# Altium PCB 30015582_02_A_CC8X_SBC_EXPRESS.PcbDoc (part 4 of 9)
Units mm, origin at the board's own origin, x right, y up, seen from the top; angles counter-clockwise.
Board outline 87 x 63 mm, 6 copper layers (Top Layer-L1, GND Plane-L2, Signal-L3, PWR/Signal-L4, GND Plane-L5, Bottom Layer-L6), stack 1.172 mm thick; 169 components, 171 nets, 693 pads, 391 vias.
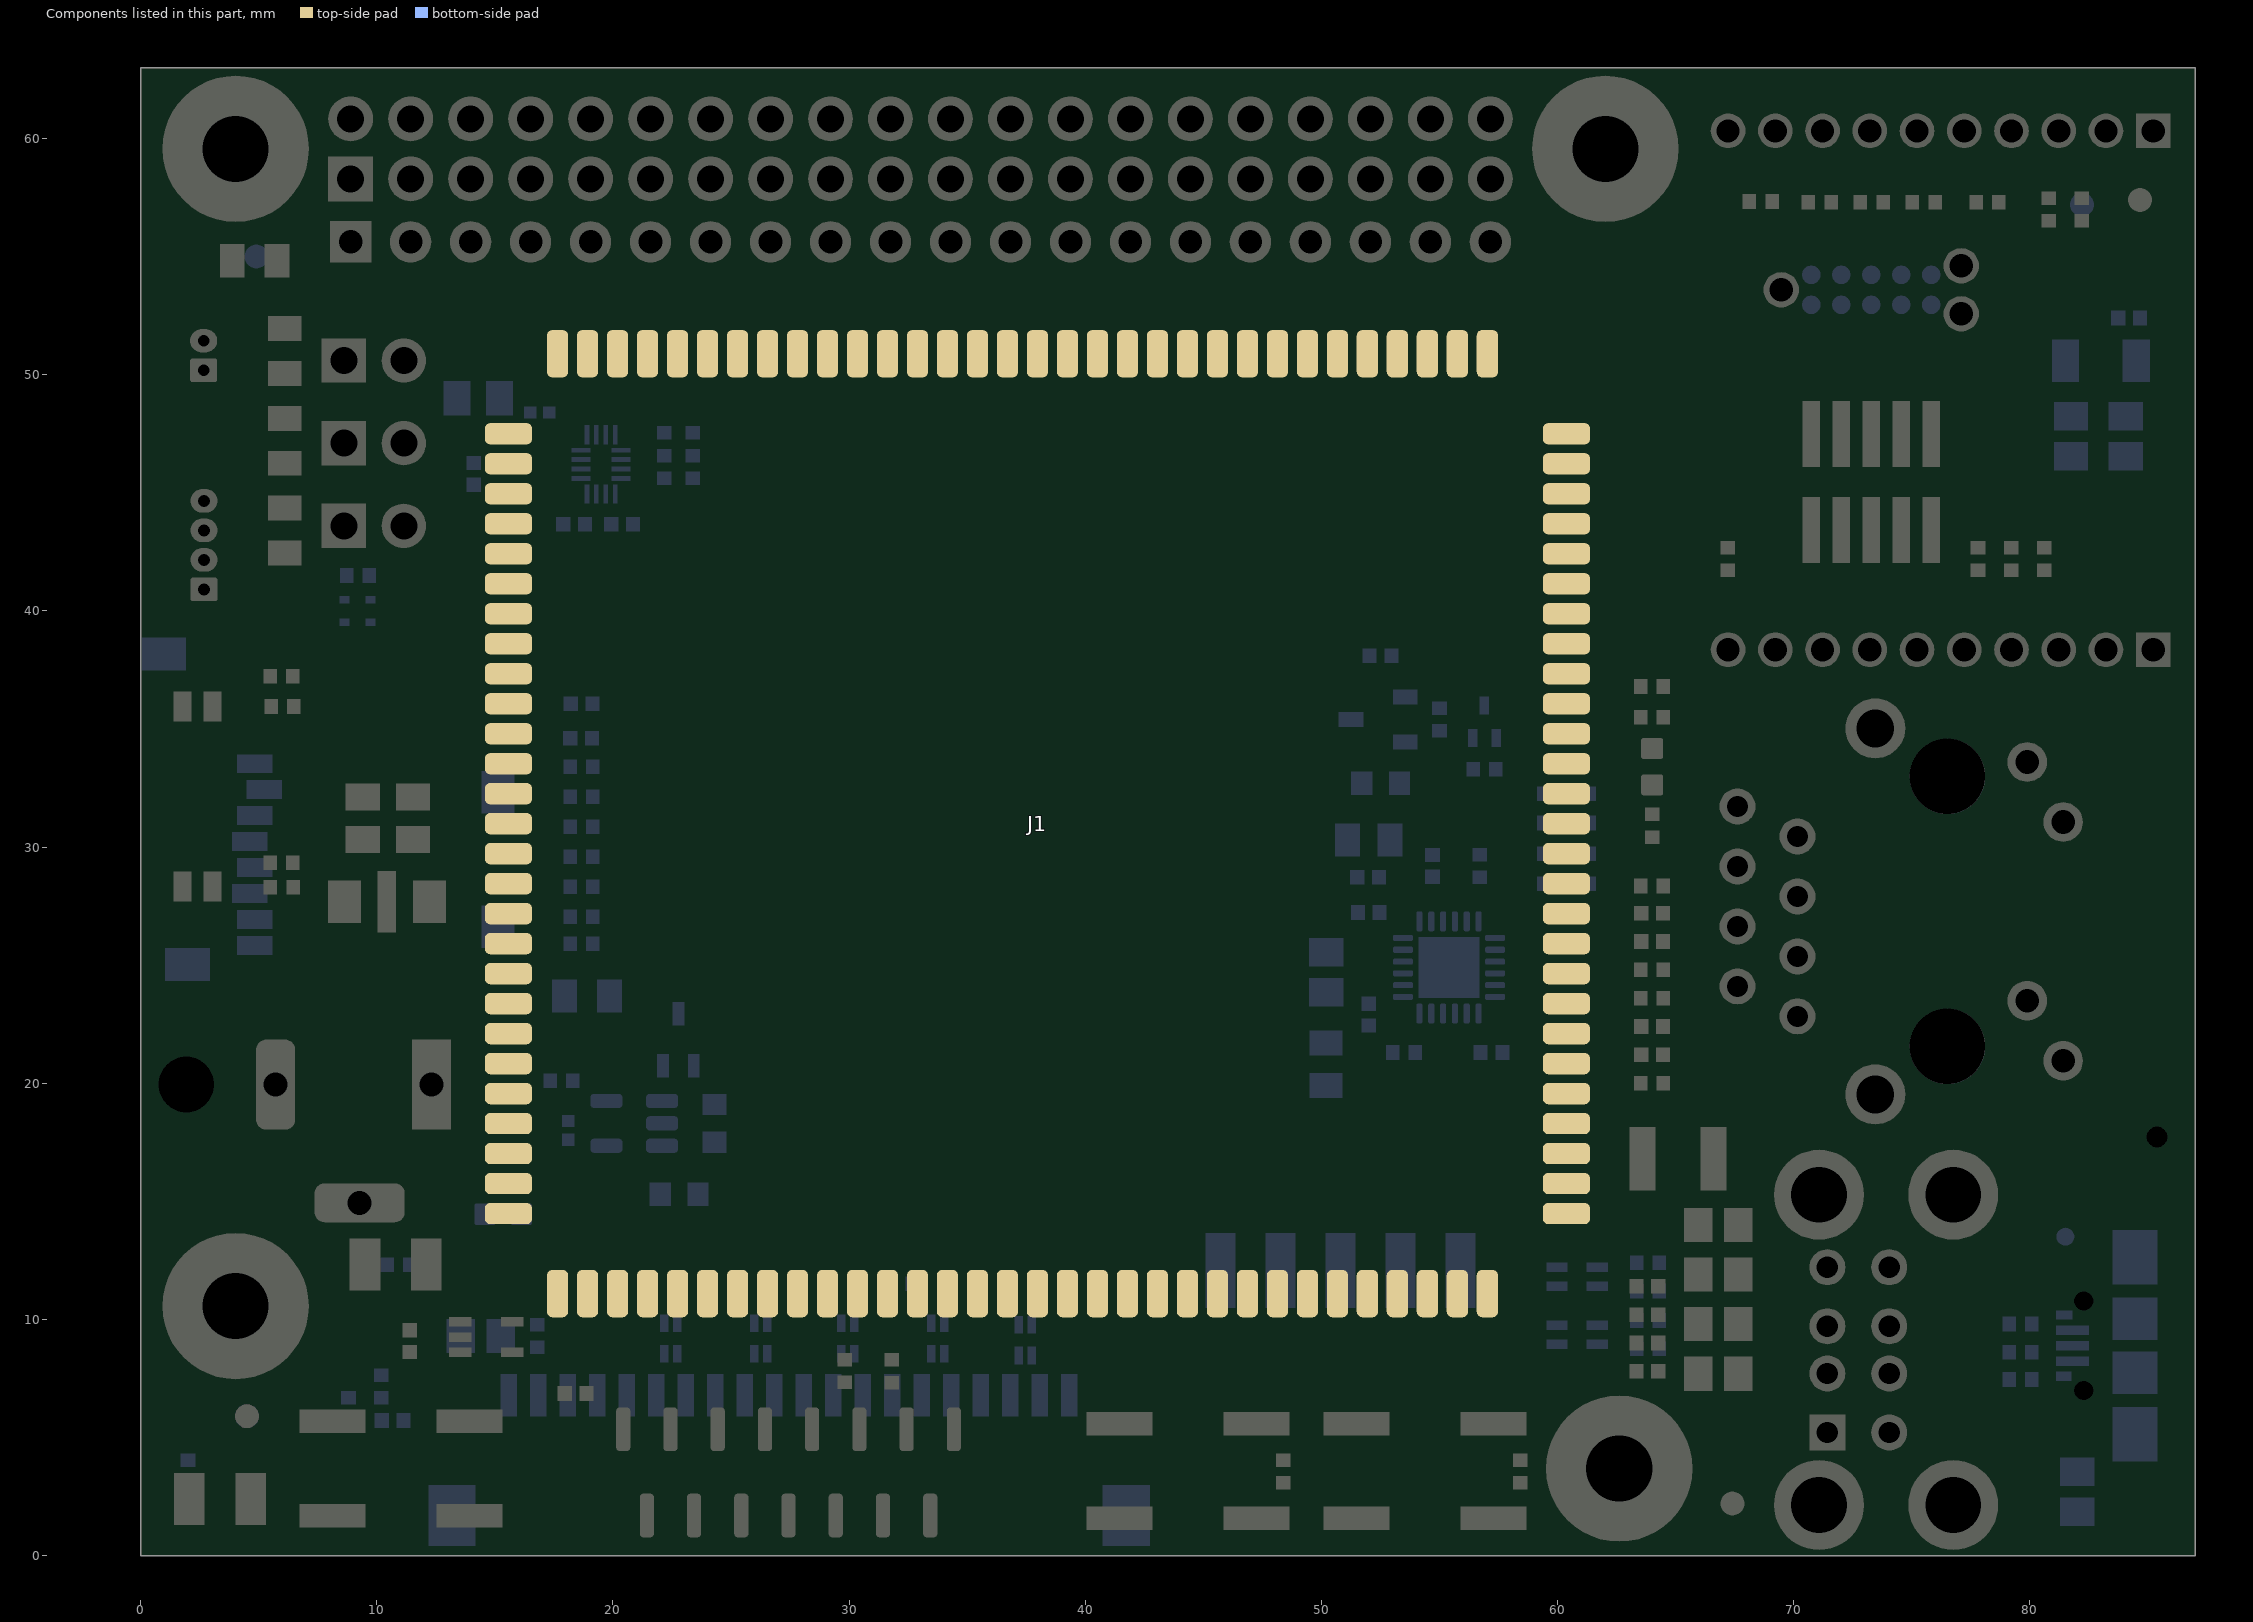
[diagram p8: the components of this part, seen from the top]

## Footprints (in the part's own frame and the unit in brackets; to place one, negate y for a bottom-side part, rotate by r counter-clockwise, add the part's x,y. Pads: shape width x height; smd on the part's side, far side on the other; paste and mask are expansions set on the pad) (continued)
CC8X_CASTELLATED [mm] (continued)
  Top Layer-L1 keep-out region: 11.63,12.7 11.615,12.777 11.571,12.841 11.507,12.885 11.43,12.9 11.43,12.9 11.353,12.885 11.289,12.841 11.245,12.777 11.23,12.7 11.23,12.7 11.245,12.623 11.289,12.559 11.353,12.515 11.43,12.5 11.43,12.5 11.507,12.515 11.571,12.559 11.615,12.623 11.63,12.7
  Top Layer-L1 keep-out region: 12.9,12.7 12.885,12.777 12.841,12.841 12.777,12.885 12.7,12.9 12.7,12.9 12.623,12.885 12.559,12.841 12.515,12.777 12.5,12.7 12.5,12.7 12.515,12.623 12.559,12.559 12.623,12.515 12.7,12.5 12.7,12.5 12.777,12.515 12.841,12.559 12.885,12.623 12.9,12.7
  Top Layer-L1 keep-out region: 14.17,12.7 14.155,12.777 14.111,12.841 14.047,12.885 13.97,12.9 13.97,12.9 13.893,12.885 13.829,12.841 13.785,12.777 13.77,12.7 13.77,12.7 13.785,12.623 13.829,12.559 13.893,12.515 13.97,12.5 13.97,12.5 14.047,12.515 14.111,12.559 14.155,12.623 14.17,12.7
  Top Layer-L1 keep-out region: 15.44,12.7 15.425,12.777 15.381,12.841 15.317,12.885 15.24,12.9 15.24,12.9 15.163,12.885 15.099,12.841 15.055,12.777 15.04,12.7 15.04,12.7 15.055,12.623 15.099,12.559 15.163,12.515 15.24,12.5 15.24,12.5 15.317,12.515 15.381,12.559 15.425,12.623 15.44,12.7
  Top Layer-L1 keep-out region: 16.71,12.7 16.695,12.777 16.651,12.841 16.587,12.885 16.51,12.9 16.51,12.9 16.433,12.885 16.369,12.841 16.325,12.777 16.31,12.7 16.31,12.7 16.325,12.623 16.369,12.559 16.433,12.515 16.51,12.5 16.51,12.5 16.587,12.515 16.651,12.559 16.695,12.623 16.71,12.7
  Top Layer-L1 keep-out region: 17.98,12.7 17.965,12.777 17.921,12.841 17.857,12.885 17.78,12.9 17.78,12.9 17.703,12.885 17.639,12.841 17.595,12.777 17.58,12.7 17.58,12.7 17.595,12.623 17.639,12.559 17.703,12.515 17.78,12.5 17.78,12.5 17.857,12.515 17.921,12.559 17.965,12.623 17.98,12.7
  Top Layer-L1 keep-out region: -17.58,13.97 -17.595,14.047 -17.639,14.111 -17.703,14.155 -17.78,14.17 -17.78,14.17 -17.857,14.155 -17.921,14.111 -17.965,14.047 -17.98,13.97 -17.98,13.97 -17.965,13.893 -17.921,13.829 -17.857,13.785 -17.78,13.77 -17.78,13.77 -17.703,13.785 -17.639,13.829 -17.595,13.893 -17.58,13.97
  Top Layer-L1 keep-out region: -16.31,13.97 -16.325,14.047 -16.369,14.111 -16.433,14.155 -16.51,14.17 -16.51,14.17 -16.587,14.155 -16.651,14.111 -16.695,14.047 -16.71,13.97 -16.71,13.97 -16.695,13.893 -16.651,13.829 -16.587,13.785 -16.51,13.77 -16.51,13.77 -16.433,13.785 -16.369,13.829 -16.325,13.893 -16.31,13.97
  Top Layer-L1 keep-out region: -15.04,13.97 -15.055,14.047 -15.099,14.111 -15.163,14.155 -15.24,14.17 -15.24,14.17 -15.317,14.155 -15.381,14.111 -15.425,14.047 -15.44,13.97 -15.44,13.97 -15.425,13.893 -15.381,13.829 -15.317,13.785 -15.24,13.77 -15.24,13.77 -15.163,13.785 -15.099,13.829 -15.055,13.893 -15.04,13.97
  Top Layer-L1 keep-out region: -13.77,13.97 -13.785,14.047 -13.829,14.111 -13.893,14.155 -13.97,14.17 -13.97,14.17 -14.047,14.155 -14.111,14.111 -14.155,14.047 -14.17,13.97 -14.17,13.97 -14.155,13.893 -14.111,13.829 -14.047,13.785 -13.97,13.77 -13.97,13.77 -13.893,13.785 -13.829,13.829 -13.785,13.893 -13.77,13.97
  Top Layer-L1 keep-out region: -12.5,13.97 -12.515,14.047 -12.559,14.111 -12.623,14.155 -12.7,14.17 -12.7,14.17 -12.777,14.155 -12.841,14.111 -12.885,14.047 -12.9,13.97 -12.9,13.97 -12.885,13.893 -12.841,13.829 -12.777,13.785 -12.7,13.77 -12.7,13.77 -12.623,13.785 -12.559,13.829 -12.515,13.893 -12.5,13.97
  Top Layer-L1 keep-out region: -11.23,13.97 -11.245,14.047 -11.289,14.111 -11.353,14.155 -11.43,14.17 -11.43,14.17 -11.507,14.155 -11.571,14.111 -11.615,14.047 -11.63,13.97 -11.63,13.97 -11.615,13.893 -11.571,13.829 -11.507,13.785 -11.43,13.77 -11.43,13.77 -11.353,13.785 -11.289,13.829 -11.245,13.893 -11.23,13.97
  Top Layer-L1 keep-out region: -9.96,13.97 -9.975,14.047 -10.019,14.111 -10.083,14.155 -10.16,14.17 -10.16,14.17 -10.237,14.155 -10.301,14.111 -10.345,14.047 -10.36,13.97 -10.36,13.97 -10.345,13.893 -10.301,13.829 -10.237,13.785 -10.16,13.77 -10.16,13.77 -10.083,13.785 -10.019,13.829 -9.975,13.893 -9.96,13.97
  Top Layer-L1 keep-out region: -8.69,13.97 -8.705,14.047 -8.749,14.111 -8.813,14.155 -8.89,14.17 -8.89,14.17 -8.967,14.155 -9.031,14.111 -9.075,14.047 -9.09,13.97 -9.09,13.97 -9.075,13.893 -9.031,13.829 -8.967,13.785 -8.89,13.77 -8.89,13.77 -8.813,13.785 -8.749,13.829 -8.705,13.893 -8.69,13.97
  Top Layer-L1 keep-out region: -7.42,13.97 -7.435,14.047 -7.479,14.111 -7.543,14.155 -7.62,14.17 -7.62,14.17 -7.697,14.155 -7.761,14.111 -7.805,14.047 -7.82,13.97 -7.82,13.97 -7.805,13.893 -7.761,13.829 -7.697,13.785 -7.62,13.77 -7.62,13.77 -7.543,13.785 -7.479,13.829 -7.435,13.893 -7.42,13.97
  Top Layer-L1 keep-out region: -6.15,13.97 -6.165,14.047 -6.209,14.111 -6.273,14.155 -6.35,14.17 -6.35,14.17 -6.427,14.155 -6.491,14.111 -6.535,14.047 -6.55,13.97 -6.55,13.97 -6.535,13.893 -6.491,13.829 -6.427,13.785 -6.35,13.77 -6.35,13.77 -6.273,13.785 -6.209,13.829 -6.165,13.893 -6.15,13.97
  Top Layer-L1 keep-out region: -4.88,13.97 -4.895,14.047 -4.939,14.111 -5.003,14.155 -5.08,14.17 -5.08,14.17 -5.157,14.155 -5.221,14.111 -5.265,14.047 -5.28,13.97 -5.28,13.97 -5.265,13.893 -5.221,13.829 -5.157,13.785 -5.08,13.77 -5.08,13.77 -5.003,13.785 -4.939,13.829 -4.895,13.893 -4.88,13.97
  Top Layer-L1 keep-out region: -3.61,13.97 -3.625,14.047 -3.669,14.111 -3.733,14.155 -3.81,14.17 -3.81,14.17 -3.887,14.155 -3.951,14.111 -3.995,14.047 -4.01,13.97 -4.01,13.97 -3.995,13.893 -3.951,13.829 -3.887,13.785 -3.81,13.77 -3.81,13.77 -3.733,13.785 -3.669,13.829 -3.625,13.893 -3.61,13.97
  Top Layer-L1 keep-out region: -2.34,13.97 -2.355,14.047 -2.399,14.111 -2.463,14.155 -2.54,14.17 -2.54,14.17 -2.617,14.155 -2.681,14.111 -2.725,14.047 -2.74,13.97 -2.74,13.97 -2.725,13.893 -2.681,13.829 -2.617,13.785 -2.54,13.77 -2.54,13.77 -2.463,13.785 -2.399,13.829 -2.355,13.893 -2.34,13.97
  Top Layer-L1 keep-out region: -1.07,13.97 -1.085,14.047 -1.129,14.111 -1.193,14.155 -1.27,14.17 -1.27,14.17 -1.347,14.155 -1.411,14.111 -1.455,14.047 -1.47,13.97 -1.47,13.97 -1.455,13.893 -1.411,13.829 -1.347,13.785 -1.27,13.77 -1.27,13.77 -1.193,13.785 -1.129,13.829 -1.085,13.893 -1.07,13.97
  Top Layer-L1 keep-out region: 0.2,13.97 0.185,14.047 0.141,14.111 0.077,14.155 0,14.17 0,14.17 -0.077,14.155 -0.141,14.111 -0.185,14.047 -0.2,13.97 -0.2,13.97 -0.185,13.893 -0.141,13.829 -0.077,13.785 0,13.77 0,13.77 0.077,13.785 0.141,13.829 0.185,13.893 0.2,13.97
  Top Layer-L1 keep-out region: 1.47,13.97 1.455,14.047 1.411,14.111 1.347,14.155 1.27,14.17 1.27,14.17 1.193,14.155 1.129,14.111 1.085,14.047 1.07,13.97 1.07,13.97 1.085,13.893 1.129,13.829 1.193,13.785 1.27,13.77 1.27,13.77 1.347,13.785 1.411,13.829 1.455,13.893 1.47,13.97
  Top Layer-L1 keep-out region: 2.74,13.97 2.725,14.047 2.681,14.111 2.617,14.155 2.54,14.17 2.54,14.17 2.463,14.155 2.399,14.111 2.355,14.047 2.34,13.97 2.34,13.97 2.355,13.893 2.399,13.829 2.463,13.785 2.54,13.77 2.54,13.77 2.617,13.785 2.681,13.829 2.725,13.893 2.74,13.97
  Top Layer-L1 keep-out region: 4.01,13.97 3.995,14.047 3.951,14.111 3.887,14.155 3.81,14.17 3.81,14.17 3.733,14.155 3.669,14.111 3.625,14.047 3.61,13.97 3.61,13.97 3.625,13.893 3.669,13.829 3.733,13.785 3.81,13.77 3.81,13.77 3.887,13.785 3.951,13.829 3.995,13.893 4.01,13.97
  Top Layer-L1 keep-out region: 5.28,13.97 5.265,14.047 5.221,14.111 5.157,14.155 5.08,14.17 5.08,14.17 5.003,14.155 4.939,14.111 4.895,14.047 4.88,13.97 4.88,13.97 4.895,13.893 4.939,13.829 5.003,13.785 5.08,13.77 5.08,13.77 5.157,13.785 5.221,13.829 5.265,13.893 5.28,13.97
  Top Layer-L1 keep-out region: 6.55,13.97 6.535,14.047 6.491,14.111 6.427,14.155 6.35,14.17 6.35,14.17 6.273,14.155 6.209,14.111 6.165,14.047 6.15,13.97 6.15,13.97 6.165,13.893 6.209,13.829 6.273,13.785 6.35,13.77 6.35,13.77 6.427,13.785 6.491,13.829 6.535,13.893 6.55,13.97
  Top Layer-L1 keep-out region: 7.82,13.97 7.805,14.047 7.761,14.111 7.697,14.155 7.62,14.17 7.62,14.17 7.543,14.155 7.479,14.111 7.435,14.047 7.42,13.97 7.42,13.97 7.435,13.893 7.479,13.829 7.543,13.785 7.62,13.77 7.62,13.77 7.697,13.785 7.761,13.829 7.805,13.893 7.82,13.97
  Top Layer-L1 keep-out region: 9.09,13.97 9.075,14.047 9.031,14.111 8.967,14.155 8.89,14.17 8.89,14.17 8.813,14.155 8.749,14.111 8.705,14.047 8.69,13.97 8.69,13.97 8.705,13.893 8.749,13.829 8.813,13.785 8.89,13.77 8.89,13.77 8.967,13.785 9.031,13.829 9.075,13.893 9.09,13.97
  Top Layer-L1 keep-out region: 10.36,13.97 10.345,14.047 10.301,14.111 10.237,14.155 10.16,14.17 10.16,14.17 10.083,14.155 10.019,14.111 9.975,14.047 9.96,13.97 9.96,13.97 9.975,13.893 10.019,13.829 10.083,13.785 10.16,13.77 10.16,13.77 10.237,13.785 10.301,13.829 10.345,13.893 10.36,13.97
  Top Layer-L1 keep-out region: 11.63,13.97 11.615,14.047 11.571,14.111 11.507,14.155 11.43,14.17 11.43,14.17 11.353,14.155 11.289,14.111 11.245,14.047 11.23,13.97 11.23,13.97 11.245,13.893 11.289,13.829 11.353,13.785 11.43,13.77 11.43,13.77 11.507,13.785 11.571,13.829 11.615,13.893 11.63,13.97
  Top Layer-L1 keep-out region: 12.9,13.97 12.885,14.047 12.841,14.111 12.777,14.155 12.7,14.17 12.7,14.17 12.623,14.155 12.559,14.111 12.515,14.047 12.5,13.97 12.5,13.97 12.515,13.893 12.559,13.829 12.623,13.785 12.7,13.77 12.7,13.77 12.777,13.785 12.841,13.829 12.885,13.893 12.9,13.97
  Top Layer-L1 keep-out region: 14.17,13.97 14.155,14.047 14.111,14.111 14.047,14.155 13.97,14.17 13.97,14.17 13.893,14.155 13.829,14.111 13.785,14.047 13.77,13.97 13.77,13.97 13.785,13.893 13.829,13.829 13.893,13.785 13.97,13.77 13.97,13.77 14.047,13.785 14.111,13.829 14.155,13.893 14.17,13.97
  Top Layer-L1 keep-out region: 15.44,13.97 15.425,14.047 15.381,14.111 15.317,14.155 15.24,14.17 15.24,14.17 15.163,14.155 15.099,14.111 15.055,14.047 15.04,13.97 15.04,13.97 15.055,13.893 15.099,13.829 15.163,13.785 15.24,13.77 15.24,13.77 15.317,13.785 15.381,13.829 15.425,13.893 15.44,13.97
  Top Layer-L1 keep-out region: 16.71,13.97 16.695,14.047 16.651,14.111 16.587,14.155 16.51,14.17 16.51,14.17 16.433,14.155 16.369,14.111 16.325,14.047 16.31,13.97 16.31,13.97 16.325,13.893 16.369,13.829 16.433,13.785 16.51,13.77 16.51,13.77 16.587,13.785 16.651,13.829 16.695,13.893 16.71,13.97
  Top Layer-L1 keep-out region: 17.98,13.97 17.965,14.047 17.921,14.111 17.857,14.155 17.78,14.17 17.78,14.17 17.703,14.155 17.639,14.111 17.595,14.047 17.58,13.97 17.58,13.97 17.595,13.893 17.639,13.829 17.703,13.785 17.78,13.77 17.78,13.77 17.857,13.785 17.921,13.829 17.965,13.893 17.98,13.97
  Top Layer-L1 keep-out region: -17.58,15.24 -17.595,15.317 -17.639,15.381 -17.703,15.425 -17.78,15.44 -17.78,15.44 -17.857,15.425 -17.921,15.381 -17.965,15.317 -17.98,15.24 -17.98,15.24 -17.965,15.163 -17.921,15.099 -17.857,15.055 -17.78,15.04 -17.78,15.04 -17.703,15.055 -17.639,15.099 -17.595,15.163 -17.58,15.24
  Top Layer-L1 keep-out region: -16.31,15.24 -16.325,15.317 -16.369,15.381 -16.433,15.425 -16.51,15.44 -16.51,15.44 -16.587,15.425 -16.651,15.381 -16.695,15.317 -16.71,15.24 -16.71,15.24 -16.695,15.163 -16.651,15.099 -16.587,15.055 -16.51,15.04 -16.51,15.04 -16.433,15.055 -16.369,15.099 -16.325,15.163 -16.31,15.24
  Top Layer-L1 keep-out region: -15.04,15.24 -15.055,15.317 -15.099,15.381 -15.163,15.425 -15.24,15.44 -15.24,15.44 -15.317,15.425 -15.381,15.381 -15.425,15.317 -15.44,15.24 -15.44,15.24 -15.425,15.163 -15.381,15.099 -15.317,15.055 -15.24,15.04 -15.24,15.04 -15.163,15.055 -15.099,15.099 -15.055,15.163 -15.04,15.24
  Top Layer-L1 keep-out region: -13.77,15.24 -13.785,15.317 -13.829,15.381 -13.893,15.425 -13.97,15.44 -13.97,15.44 -14.047,15.425 -14.111,15.381 -14.155,15.317 -14.17,15.24 -14.17,15.24 -14.155,15.163 -14.111,15.099 -14.047,15.055 -13.97,15.04 -13.97,15.04 -13.893,15.055 -13.829,15.099 -13.785,15.163 -13.77,15.24
  Top Layer-L1 keep-out region: -12.5,15.24 -12.515,15.317 -12.559,15.381 -12.623,15.425 -12.7,15.44 -12.7,15.44 -12.777,15.425 -12.841,15.381 -12.885,15.317 -12.9,15.24 -12.9,15.24 -12.885,15.163 -12.841,15.099 -12.777,15.055 -12.7,15.04 -12.7,15.04 -12.623,15.055 -12.559,15.099 -12.515,15.163 -12.5,15.24
  Top Layer-L1 keep-out region: -11.23,15.24 -11.245,15.317 -11.289,15.381 -11.353,15.425 -11.43,15.44 -11.43,15.44 -11.507,15.425 -11.571,15.381 -11.615,15.317 -11.63,15.24 -11.63,15.24 -11.615,15.163 -11.571,15.099 -11.507,15.055 -11.43,15.04 -11.43,15.04 -11.353,15.055 -11.289,15.099 -11.245,15.163 -11.23,15.24
  Top Layer-L1 keep-out region: -9.96,15.24 -9.975,15.317 -10.019,15.381 -10.083,15.425 -10.16,15.44 -10.16,15.44 -10.237,15.425 -10.301,15.381 -10.345,15.317 -10.36,15.24 -10.36,15.24 -10.345,15.163 -10.301,15.099 -10.237,15.055 -10.16,15.04 -10.16,15.04 -10.083,15.055 -10.019,15.099 -9.975,15.163 -9.96,15.24
  Top Layer-L1 keep-out region: -8.69,15.24 -8.705,15.317 -8.749,15.381 -8.813,15.425 -8.89,15.44 -8.89,15.44 -8.967,15.425 -9.031,15.381 -9.075,15.317 -9.09,15.24 -9.09,15.24 -9.075,15.163 -9.031,15.099 -8.967,15.055 -8.89,15.04 -8.89,15.04 -8.813,15.055 -8.749,15.099 -8.705,15.163 -8.69,15.24
  Top Layer-L1 keep-out region: -7.42,15.24 -7.435,15.317 -7.479,15.381 -7.543,15.425 -7.62,15.44 -7.62,15.44 -7.697,15.425 -7.761,15.381 -7.805,15.317 -7.82,15.24 -7.82,15.24 -7.805,15.163 -7.761,15.099 -7.697,15.055 -7.62,15.04 -7.62,15.04 -7.543,15.055 -7.479,15.099 -7.435,15.163 -7.42,15.24
  Top Layer-L1 keep-out region: -6.15,15.24 -6.165,15.317 -6.209,15.381 -6.273,15.425 -6.35,15.44 -6.35,15.44 -6.427,15.425 -6.491,15.381 -6.535,15.317 -6.55,15.24 -6.55,15.24 -6.535,15.163 -6.491,15.099 -6.427,15.055 -6.35,15.04 -6.35,15.04 -6.273,15.055 -6.209,15.099 -6.165,15.163 -6.15,15.24
  Top Layer-L1 keep-out region: -4.88,15.24 -4.895,15.317 -4.939,15.381 -5.003,15.425 -5.08,15.44 -5.08,15.44 -5.157,15.425 -5.221,15.381 -5.265,15.317 -5.28,15.24 -5.28,15.24 -5.265,15.163 -5.221,15.099 -5.157,15.055 -5.08,15.04 -5.08,15.04 -5.003,15.055 -4.939,15.099 -4.895,15.163 -4.88,15.24
  Top Layer-L1 keep-out region: -3.61,15.24 -3.625,15.317 -3.669,15.381 -3.733,15.425 -3.81,15.44 -3.81,15.44 -3.887,15.425 -3.951,15.381 -3.995,15.317 -4.01,15.24 -4.01,15.24 -3.995,15.163 -3.951,15.099 -3.887,15.055 -3.81,15.04 -3.81,15.04 -3.733,15.055 -3.669,15.099 -3.625,15.163 -3.61,15.24
  Top Layer-L1 keep-out region: -2.34,15.24 -2.355,15.317 -2.399,15.381 -2.463,15.425 -2.54,15.44 -2.54,15.44 -2.617,15.425 -2.681,15.381 -2.725,15.317 -2.74,15.24 -2.74,15.24 -2.725,15.163 -2.681,15.099 -2.617,15.055 -2.54,15.04 -2.54,15.04 -2.463,15.055 -2.399,15.099 -2.355,15.163 -2.34,15.24
  Top Layer-L1 keep-out region: -1.07,15.24 -1.085,15.317 -1.129,15.381 -1.193,15.425 -1.27,15.44 -1.27,15.44 -1.347,15.425 -1.411,15.381 -1.455,15.317 -1.47,15.24 -1.47,15.24 -1.455,15.163 -1.411,15.099 -1.347,15.055 -1.27,15.04 -1.27,15.04 -1.193,15.055 -1.129,15.099 -1.085,15.163 -1.07,15.24
  Top Layer-L1 keep-out region: 0.2,15.24 0.185,15.317 0.141,15.381 0.077,15.425 0,15.44 0,15.44 -0.077,15.425 -0.141,15.381 -0.185,15.317 -0.2,15.24 -0.2,15.24 -0.185,15.163 -0.141,15.099 -0.077,15.055 0,15.04 0,15.04 0.077,15.055 0.141,15.099 0.185,15.163 0.2,15.24
  Top Layer-L1 keep-out region: 1.47,15.24 1.455,15.317 1.411,15.381 1.347,15.425 1.27,15.44 1.27,15.44 1.193,15.425 1.129,15.381 1.085,15.317 1.07,15.24 1.07,15.24 1.085,15.163 1.129,15.099 1.193,15.055 1.27,15.04 1.27,15.04 1.347,15.055 1.411,15.099 1.455,15.163 1.47,15.24
  Top Layer-L1 keep-out region: 2.74,15.24 2.725,15.317 2.681,15.381 2.617,15.425 2.54,15.44 2.54,15.44 2.463,15.425 2.399,15.381 2.355,15.317 2.34,15.24 2.34,15.24 2.355,15.163 2.399,15.099 2.463,15.055 2.54,15.04 2.54,15.04 2.617,15.055 2.681,15.099 2.725,15.163 2.74,15.24
  Top Layer-L1 keep-out region: 4.01,15.24 3.995,15.317 3.951,15.381 3.887,15.425 3.81,15.44 3.81,15.44 3.733,15.425 3.669,15.381 3.625,15.317 3.61,15.24 3.61,15.24 3.625,15.163 3.669,15.099 3.733,15.055 3.81,15.04 3.81,15.04 3.887,15.055 3.951,15.099 3.995,15.163 4.01,15.24
  Top Layer-L1 keep-out region: 5.28,15.24 5.265,15.317 5.221,15.381 5.157,15.425 5.08,15.44 5.08,15.44 5.003,15.425 4.939,15.381 4.895,15.317 4.88,15.24 4.88,15.24 4.895,15.163 4.939,15.099 5.003,15.055 5.08,15.04 5.08,15.04 5.157,15.055 5.221,15.099 5.265,15.163 5.28,15.24
  Top Layer-L1 keep-out region: 6.55,15.24 6.535,15.317 6.491,15.381 6.427,15.425 6.35,15.44 6.35,15.44 6.273,15.425 6.209,15.381 6.165,15.317 6.15,15.24 6.15,15.24 6.165,15.163 6.209,15.099 6.273,15.055 6.35,15.04 6.35,15.04 6.427,15.055 6.491,15.099 6.535,15.163 6.55,15.24
  Top Layer-L1 keep-out region: 7.82,15.24 7.805,15.317 7.761,15.381 7.697,15.425 7.62,15.44 7.62,15.44 7.543,15.425 7.479,15.381 7.435,15.317 7.42,15.24 7.42,15.24 7.435,15.163 7.479,15.099 7.543,15.055 7.62,15.04 7.62,15.04 7.697,15.055 7.761,15.099 7.805,15.163 7.82,15.24
  Top Layer-L1 keep-out region: 9.09,15.24 9.075,15.317 9.031,15.381 8.967,15.425 8.89,15.44 8.89,15.44 8.813,15.425 8.749,15.381 8.705,15.317 8.69,15.24 8.69,15.24 8.705,15.163 8.749,15.099 8.813,15.055 8.89,15.04 8.89,15.04 8.967,15.055 9.031,15.099 9.075,15.163 9.09,15.24
  Top Layer-L1 keep-out region: 10.36,15.24 10.345,15.317 10.301,15.381 10.237,15.425 10.16,15.44 10.16,15.44 10.083,15.425 10.019,15.381 9.975,15.317 9.96,15.24 9.96,15.24 9.975,15.163 10.019,15.099 10.083,15.055 10.16,15.04 10.16,15.04 10.237,15.055 10.301,15.099 10.345,15.163 10.36,15.24
  Top Layer-L1 keep-out region: 11.63,15.24 11.615,15.317 11.571,15.381 11.507,15.425 11.43,15.44 11.43,15.44 11.353,15.425 11.289,15.381 11.245,15.317 11.23,15.24 11.23,15.24 11.245,15.163 11.289,15.099 11.353,15.055 11.43,15.04 11.43,15.04 11.507,15.055 11.571,15.099 11.615,15.163 11.63,15.24
  Top Layer-L1 keep-out region: 12.9,15.24 12.885,15.317 12.841,15.381 12.777,15.425 12.7,15.44 12.7,15.44 12.623,15.425 12.559,15.381 12.515,15.317 12.5,15.24 12.5,15.24 12.515,15.163 12.559,15.099 12.623,15.055 12.7,15.04 12.7,15.04 12.777,15.055 12.841,15.099 12.885,15.163 12.9,15.24
  Top Layer-L1 keep-out region: 14.17,15.24 14.155,15.317 14.111,15.381 14.047,15.425 13.97,15.44 13.97,15.44 13.893,15.425 13.829,15.381 13.785,15.317 13.77,15.24 13.77,15.24 13.785,15.163 13.829,15.099 13.893,15.055 13.97,15.04 13.97,15.04 14.047,15.055 14.111,15.099 14.155,15.163 14.17,15.24
  Top Layer-L1 keep-out region: 15.44,15.24 15.425,15.317 15.381,15.381 15.317,15.425 15.24,15.44 15.24,15.44 15.163,15.425 15.099,15.381 15.055,15.317 15.04,15.24 15.04,15.24 15.055,15.163 15.099,15.099 15.163,15.055 15.24,15.04 15.24,15.04 15.317,15.055 15.381,15.099 15.425,15.163 15.44,15.24
  Top Layer-L1 keep-out region: 16.71,15.24 16.695,15.317 16.651,15.381 16.587,15.425 16.51,15.44 16.51,15.44 16.433,15.425 16.369,15.381 16.325,15.317 16.31,15.24 16.31,15.24 16.325,15.163 16.369,15.099 16.433,15.055 16.51,15.04 16.51,15.04 16.587,15.055 16.651,15.099 16.695,15.163 16.71,15.24
  Top Layer-L1 keep-out region: 17.98,15.24 17.965,15.317 17.921,15.381 17.857,15.425 17.78,15.44 17.78,15.44 17.703,15.425 17.639,15.381 17.595,15.317 17.58,15.24 17.58,15.24 17.595,15.163 17.639,15.099 17.703,15.055 17.78,15.04 17.78,15.04 17.857,15.055 17.921,15.099 17.965,15.163 17.98,15.24
  Top Layer-L1 keep-out region: -17.58,16.51 -17.595,16.587 -17.639,16.651 -17.703,16.695 -17.78,16.71 -17.78,16.71 -17.857,16.695 -17.921,16.651 -17.965,16.587 -17.98,16.51 -17.98,16.51 -17.965,16.433 -17.921,16.369 -17.857,16.325 -17.78,16.31 -17.78,16.31 -17.703,16.325 -17.639,16.369 -17.595,16.433 -17.58,16.51
  Top Layer-L1 keep-out region: -16.31,16.51 -16.325,16.587 -16.369,16.651 -16.433,16.695 -16.51,16.71 -16.51,16.71 -16.587,16.695 -16.651,16.651 -16.695,16.587 -16.71,16.51 -16.71,16.51 -16.695,16.433 -16.651,16.369 -16.587,16.325 -16.51,16.31 -16.51,16.31 -16.433,16.325 -16.369,16.369 -16.325,16.433 -16.31,16.51
  Top Layer-L1 keep-out region: -15.04,16.51 -15.055,16.587 -15.099,16.651 -15.163,16.695 -15.24,16.71 -15.24,16.71 -15.317,16.695 -15.381,16.651 -15.425,16.587 -15.44,16.51 -15.44,16.51 -15.425,16.433 -15.381,16.369 -15.317,16.325 -15.24,16.31 -15.24,16.31 -15.163,16.325 -15.099,16.369 -15.055,16.433 -15.04,16.51
  Top Layer-L1 keep-out region: -13.77,16.51 -13.785,16.587 -13.829,16.651 -13.893,16.695 -13.97,16.71 -13.97,16.71 -14.047,16.695 -14.111,16.651 -14.155,16.587 -14.17,16.51 -14.17,16.51 -14.155,16.433 -14.111,16.369 -14.047,16.325 -13.97,16.31 -13.97,16.31 -13.893,16.325 -13.829,16.369 -13.785,16.433 -13.77,16.51
  Top Layer-L1 keep-out region: -12.5,16.51 -12.515,16.587 -12.559,16.651 -12.623,16.695 -12.7,16.71 -12.7,16.71 -12.777,16.695 -12.841,16.651 -12.885,16.587 -12.9,16.51 -12.9,16.51 -12.885,16.433 -12.841,16.369 -12.777,16.325 -12.7,16.31 -12.7,16.31 -12.623,16.325 -12.559,16.369 -12.515,16.433 -12.5,16.51
  Top Layer-L1 keep-out region: -11.23,16.51 -11.245,16.587 -11.289,16.651 -11.353,16.695 -11.43,16.71 -11.43,16.71 -11.507,16.695 -11.571,16.651 -11.615,16.587 -11.63,16.51 -11.63,16.51 -11.615,16.433 -11.571,16.369 -11.507,16.325 -11.43,16.31 -11.43,16.31 -11.353,16.325 -11.289,16.369 -11.245,16.433 -11.23,16.51
  Top Layer-L1 keep-out region: -9.96,16.51 -9.975,16.587 -10.019,16.651 -10.083,16.695 -10.16,16.71 -10.16,16.71 -10.237,16.695 -10.301,16.651 -10.345,16.587 -10.36,16.51 -10.36,16.51 -10.345,16.433 -10.301,16.369 -10.237,16.325 -10.16,16.31 -10.16,16.31 -10.083,16.325 -10.019,16.369 -9.975,16.433 -9.96,16.51
  Top Layer-L1 keep-out region: -8.69,16.51 -8.705,16.587 -8.749,16.651 -8.813,16.695 -8.89,16.71 -8.89,16.71 -8.967,16.695 -9.031,16.651 -9.075,16.587 -9.09,16.51 -9.09,16.51 -9.075,16.433 -9.031,16.369 -8.967,16.325 -8.89,16.31 -8.89,16.31 -8.813,16.325 -8.749,16.369 -8.705,16.433 -8.69,16.51
  Top Layer-L1 keep-out region: -7.42,16.51 -7.435,16.587 -7.479,16.651 -7.543,16.695 -7.62,16.71 -7.62,16.71 -7.697,16.695 -7.761,16.651 -7.805,16.587 -7.82,16.51 -7.82,16.51 -7.805,16.433 -7.761,16.369 -7.697,16.325 -7.62,16.31 -7.62,16.31 -7.543,16.325 -7.479,16.369 -7.435,16.433 -7.42,16.51
  Top Layer-L1 keep-out region: -6.15,16.51 -6.165,16.587 -6.209,16.651 -6.273,16.695 -6.35,16.71 -6.35,16.71 -6.427,16.695 -6.491,16.651 -6.535,16.587 -6.55,16.51 -6.55,16.51 -6.535,16.433 -6.491,16.369 -6.427,16.325 -6.35,16.31 -6.35,16.31 -6.273,16.325 -6.209,16.369 -6.165,16.433 -6.15,16.51
  Top Layer-L1 keep-out region: -4.88,16.51 -4.895,16.587 -4.939,16.651 -5.003,16.695 -5.08,16.71 -5.08,16.71 -5.157,16.695 -5.221,16.651 -5.265,16.587 -5.28,16.51 -5.28,16.51 -5.265,16.433 -5.221,16.369 -5.157,16.325 -5.08,16.31 -5.08,16.31 -5.003,16.325 -4.939,16.369 -4.895,16.433 -4.88,16.51
  Top Layer-L1 keep-out region: -3.61,16.51 -3.625,16.587 -3.669,16.651 -3.733,16.695 -3.81,16.71 -3.81,16.71 -3.887,16.695 -3.951,16.651 -3.995,16.587 -4.01,16.51 -4.01,16.51 -3.995,16.433 -3.951,16.369 -3.887,16.325 -3.81,16.31 -3.81,16.31 -3.733,16.325 -3.669,16.369 -3.625,16.433 -3.61,16.51
  Top Layer-L1 keep-out region: -2.34,16.51 -2.355,16.587 -2.399,16.651 -2.463,16.695 -2.54,16.71 -2.54,16.71 -2.617,16.695 -2.681,16.651 -2.725,16.587 -2.74,16.51 -2.74,16.51 -2.725,16.433 -2.681,16.369 -2.617,16.325 -2.54,16.31 -2.54,16.31 -2.463,16.325 -2.399,16.369 -2.355,16.433 -2.34,16.51
  Top Layer-L1 keep-out region: -1.07,16.51 -1.085,16.587 -1.129,16.651 -1.193,16.695 -1.27,16.71 -1.27,16.71 -1.347,16.695 -1.411,16.651 -1.455,16.587 -1.47,16.51 -1.47,16.51 -1.455,16.433 -1.411,16.369 -1.347,16.325 -1.27,16.31 -1.27,16.31 -1.193,16.325 -1.129,16.369 -1.085,16.433 -1.07,16.51
  Top Layer-L1 keep-out region: 0.2,16.51 0.185,16.587 0.141,16.651 0.077,16.695 0,16.71 0,16.71 -0.077,16.695 -0.141,16.651 -0.185,16.587 -0.2,16.51 -0.2,16.51 -0.185,16.433 -0.141,16.369 -0.077,16.325 0,16.31 0,16.31 0.077,16.325 0.141,16.369 0.185,16.433 0.2,16.51
  Top Layer-L1 keep-out region: 1.47,16.51 1.455,16.587 1.411,16.651 1.347,16.695 1.27,16.71 1.27,16.71 1.193,16.695 1.129,16.651 1.085,16.587 1.07,16.51 1.07,16.51 1.085,16.433 1.129,16.369 1.193,16.325 1.27,16.31 1.27,16.31 1.347,16.325 1.411,16.369 1.455,16.433 1.47,16.51
  Top Layer-L1 keep-out region: 2.74,16.51 2.725,16.587 2.681,16.651 2.617,16.695 2.54,16.71 2.54,16.71 2.463,16.695 2.399,16.651 2.355,16.587 2.34,16.51 2.34,16.51 2.355,16.433 2.399,16.369 2.463,16.325 2.54,16.31 2.54,16.31 2.617,16.325 2.681,16.369 2.725,16.433 2.74,16.51
  Top Layer-L1 keep-out region: 4.01,16.51 3.995,16.587 3.951,16.651 3.887,16.695 3.81,16.71 3.81,16.71 3.733,16.695 3.669,16.651 3.625,16.587 3.61,16.51 3.61,16.51 3.625,16.433 3.669,16.369 3.733,16.325 3.81,16.31 3.81,16.31 3.887,16.325 3.951,16.369 3.995,16.433 4.01,16.51
  Top Layer-L1 keep-out region: 5.28,16.51 5.265,16.587 5.221,16.651 5.157,16.695 5.08,16.71 5.08,16.71 5.003,16.695 4.939,16.651 4.895,16.587 4.88,16.51 4.88,16.51 4.895,16.433 4.939,16.369 5.003,16.325 5.08,16.31 5.08,16.31 5.157,16.325 5.221,16.369 5.265,16.433 5.28,16.51
  Top Layer-L1 keep-out region: 6.55,16.51 6.535,16.587 6.491,16.651 6.427,16.695 6.35,16.71 6.35,16.71 6.273,16.695 6.209,16.651 6.165,16.587 6.15,16.51 6.15,16.51 6.165,16.433 6.209,16.369 6.273,16.325 6.35,16.31 6.35,16.31 6.427,16.325 6.491,16.369 6.535,16.433 6.55,16.51
  Top Layer-L1 keep-out region: 7.82,16.51 7.805,16.587 7.761,16.651 7.697,16.695 7.62,16.71 7.62,16.71 7.543,16.695 7.479,16.651 7.435,16.587 7.42,16.51 7.42,16.51 7.435,16.433 7.479,16.369 7.543,16.325 7.62,16.31 7.62,16.31 7.697,16.325 7.761,16.369 7.805,16.433 7.82,16.51
  Top Layer-L1 keep-out region: 9.09,16.51 9.075,16.587 9.031,16.651 8.967,16.695 8.89,16.71 8.89,16.71 8.813,16.695 8.749,16.651 8.705,16.587 8.69,16.51 8.69,16.51 8.705,16.433 8.749,16.369 8.813,16.325 8.89,16.31 8.89,16.31 8.967,16.325 9.031,16.369 9.075,16.433 9.09,16.51
  Top Layer-L1 keep-out region: 10.36,16.51 10.345,16.587 10.301,16.651 10.237,16.695 10.16,16.71 10.16,16.71 10.083,16.695 10.019,16.651 9.975,16.587 9.96,16.51 9.96,16.51 9.975,16.433 10.019,16.369 10.083,16.325 10.16,16.31 10.16,16.31 10.237,16.325 10.301,16.369 10.345,16.433 10.36,16.51
  Top Layer-L1 keep-out region: 11.63,16.51 11.615,16.587 11.571,16.651 11.507,16.695 11.43,16.71 11.43,16.71 11.353,16.695 11.289,16.651 11.245,16.587 11.23,16.51 11.23,16.51 11.245,16.433 11.289,16.369 11.353,16.325 11.43,16.31 11.43,16.31 11.507,16.325 11.571,16.369 11.615,16.433 11.63,16.51
  Top Layer-L1 keep-out region: 12.9,16.51 12.885,16.587 12.841,16.651 12.777,16.695 12.7,16.71 12.7,16.71 12.623,16.695 12.559,16.651 12.515,16.587 12.5,16.51 12.5,16.51 12.515,16.433 12.559,16.369 12.623,16.325 12.7,16.31 12.7,16.31 12.777,16.325 12.841,16.369 12.885,16.433 12.9,16.51
  Top Layer-L1 keep-out region: 14.17,16.51 14.155,16.587 14.111,16.651 14.047,16.695 13.97,16.71 13.97,16.71 13.893,16.695 13.829,16.651 13.785,16.587 13.77,16.51 13.77,16.51 13.785,16.433 13.829,16.369 13.893,16.325 13.97,16.31 13.97,16.31 14.047,16.325 14.111,16.369 14.155,16.433 14.17,16.51
  Top Layer-L1 keep-out region: 15.44,16.51 15.425,16.587 15.381,16.651 15.317,16.695 15.24,16.71 15.24,16.71 15.163,16.695 15.099,16.651 15.055,16.587 15.04,16.51 15.04,16.51 15.055,16.433 15.099,16.369 15.163,16.325 15.24,16.31 15.24,16.31 15.317,16.325 15.381,16.369 15.425,16.433 15.44,16.51
  Top Layer-L1 keep-out region: 16.71,16.51 16.695,16.587 16.651,16.651 16.587,16.695 16.51,16.71 16.51,16.71 16.433,16.695 16.369,16.651 16.325,16.587 16.31,16.51 16.31,16.51 16.325,16.433 16.369,16.369 16.433,16.325 16.51,16.31 16.51,16.31 16.587,16.325 16.651,16.369 16.695,16.433 16.71,16.51
  Top Layer-L1 keep-out region: 17.98,16.51 17.965,16.587 17.921,16.651 17.857,16.695 17.78,16.71 17.78,16.71 17.703,16.695 17.639,16.651 17.595,16.587 17.58,16.51 17.58,16.51 17.595,16.433 17.639,16.369 17.703,16.325 17.78,16.31 17.78,16.31 17.857,16.325 17.921,16.369 17.965,16.433 17.98,16.51
  Top Layer-L1 keep-out region: -16.31,17.78 -16.325,17.857 -16.369,17.921 -16.433,17.965 -16.51,17.98 -16.51,17.98 -16.587,17.965 -16.651,17.921 -16.695,17.857 -16.71,17.78 -16.71,17.78 -16.695,17.703 -16.651,17.639 -16.587,17.595 -16.51,17.58 -16.51,17.58 -16.433,17.595 -16.369,17.639 -16.325,17.703 -16.31,17.78
  Top Layer-L1 keep-out region: -15.04,17.78 -15.055,17.857 -15.099,17.921 -15.163,17.965 -15.24,17.98 -15.24,17.98 -15.317,17.965 -15.381,17.921 -15.425,17.857 -15.44,17.78 -15.44,17.78 -15.425,17.703 -15.381,17.639 -15.317,17.595 -15.24,17.58 -15.24,17.58 -15.163,17.595 -15.099,17.639 -15.055,17.703 -15.04,17.78
  Top Layer-L1 keep-out region: -13.77,17.78 -13.785,17.857 -13.829,17.921 -13.893,17.965 -13.97,17.98 -13.97,17.98 -14.047,17.965 -14.111,17.921 -14.155,17.857 -14.17,17.78 -14.17,17.78 -14.155,17.703 -14.111,17.639 -14.047,17.595 -13.97,17.58 -13.97,17.58 -13.893,17.595 -13.829,17.639 -13.785,17.703 -13.77,17.78
  Top Layer-L1 keep-out region: -12.5,17.78 -12.515,17.857 -12.559,17.921 -12.623,17.965 -12.7,17.98 -12.7,17.98 -12.777,17.965 -12.841,17.921 -12.885,17.857 -12.9,17.78 -12.9,17.78 -12.885,17.703 -12.841,17.639 -12.777,17.595 -12.7,17.58 -12.7,17.58 -12.623,17.595 -12.559,17.639 -12.515,17.703 -12.5,17.78
  Top Layer-L1 keep-out region: -11.23,17.78 -11.245,17.857 -11.289,17.921 -11.353,17.965 -11.43,17.98 -11.43,17.98 -11.507,17.965 -11.571,17.921 -11.615,17.857 -11.63,17.78 -11.63,17.78 -11.615,17.703 -11.571,17.639 -11.507,17.595 -11.43,17.58 -11.43,17.58 -11.353,17.595 -11.289,17.639 -11.245,17.703 -11.23,17.78
  Top Layer-L1 keep-out region: -9.96,17.78 -9.975,17.857 -10.019,17.921 -10.083,17.965 -10.16,17.98 -10.16,17.98 -10.237,17.965 -10.301,17.921 -10.345,17.857 -10.36,17.78 -10.36,17.78 -10.345,17.703 -10.301,17.639 -10.237,17.595 -10.16,17.58 -10.16,17.58 -10.083,17.595 -10.019,17.639 -9.975,17.703 -9.96,17.78
  Top Layer-L1 keep-out region: -8.69,17.78 -8.705,17.857 -8.749,17.921 -8.813,17.965 -8.89,17.98 -8.89,17.98 -8.967,17.965 -9.031,17.921 -9.075,17.857 -9.09,17.78 -9.09,17.78 -9.075,17.703 -9.031,17.639 -8.967,17.595 -8.89,17.58 -8.89,17.58 -8.813,17.595 -8.749,17.639 -8.705,17.703 -8.69,17.78
  Top Layer-L1 keep-out region: -7.42,17.78 -7.435,17.857 -7.479,17.921 -7.543,17.965 -7.62,17.98 -7.62,17.98 -7.697,17.965 -7.761,17.921 -7.805,17.857 -7.82,17.78 -7.82,17.78 -7.805,17.703 -7.761,17.639 -7.697,17.595 -7.62,17.58 -7.62,17.58 -7.543,17.595 -7.479,17.639 -7.435,17.703 -7.42,17.78
  Top Layer-L1 keep-out region: -6.15,17.78 -6.165,17.857 -6.209,17.921 -6.273,17.965 -6.35,17.98 -6.35,17.98 -6.427,17.965 -6.491,17.921 -6.535,17.857 -6.55,17.78 -6.55,17.78 -6.535,17.703 -6.491,17.639 -6.427,17.595 -6.35,17.58 -6.35,17.58 -6.273,17.595 -6.209,17.639 -6.165,17.703 -6.15,17.78
  Top Layer-L1 keep-out region: -4.88,17.78 -4.895,17.857 -4.939,17.921 -5.003,17.965 -5.08,17.98 -5.08,17.98 -5.157,17.965 -5.221,17.921 -5.265,17.857 -5.28,17.78 -5.28,17.78 -5.265,17.703 -5.221,17.639 -5.157,17.595 -5.08,17.58 -5.08,17.58 -5.003,17.595 -4.939,17.639 -4.895,17.703 -4.88,17.78
  Top Layer-L1 keep-out region: -3.61,17.78 -3.625,17.857 -3.669,17.921 -3.733,17.965 -3.81,17.98 -3.81,17.98 -3.887,17.965 -3.951,17.921 -3.995,17.857 -4.01,17.78 -4.01,17.78 -3.995,17.703 -3.951,17.639 -3.887,17.595 -3.81,17.58 -3.81,17.58 -3.733,17.595 -3.669,17.639 -3.625,17.703 -3.61,17.78
  Top Layer-L1 keep-out region: -2.34,17.78 -2.355,17.857 -2.399,17.921 -2.463,17.965 -2.54,17.98 -2.54,17.98 -2.617,17.965 -2.681,17.921 -2.725,17.857 -2.74,17.78 -2.74,17.78 -2.725,17.703 -2.681,17.639 -2.617,17.595 -2.54,17.58 -2.54,17.58 -2.463,17.595 -2.399,17.639 -2.355,17.703 -2.34,17.78
  Top Layer-L1 keep-out region: -1.07,17.78 -1.085,17.857 -1.129,17.921 -1.193,17.965 -1.27,17.98 -1.27,17.98 -1.347,17.965 -1.411,17.921 -1.455,17.857 -1.47,17.78 -1.47,17.78 -1.455,17.703 -1.411,17.639 -1.347,17.595 -1.27,17.58 -1.27,17.58 -1.193,17.595 -1.129,17.639 -1.085,17.703 -1.07,17.78
  Top Layer-L1 keep-out region: 0.2,17.78 0.185,17.857 0.141,17.921 0.077,17.965 0,17.98 0,17.98 -0.077,17.965 -0.141,17.921 -0.185,17.857 -0.2,17.78 -0.2,17.78 -0.185,17.703 -0.141,17.639 -0.077,17.595 0,17.58 0,17.58 0.077,17.595 0.141,17.639 0.185,17.703 0.2,17.78
  Top Layer-L1 keep-out region: 1.47,17.78 1.455,17.857 1.411,17.921 1.347,17.965 1.27,17.98 1.27,17.98 1.193,17.965 1.129,17.921 1.085,17.857 1.07,17.78 1.07,17.78 1.085,17.703 1.129,17.639 1.193,17.595 1.27,17.58 1.27,17.58 1.347,17.595 1.411,17.639 1.455,17.703 1.47,17.78
  Top Layer-L1 keep-out region: 2.74,17.78 2.725,17.857 2.681,17.921 2.617,17.965 2.54,17.98 2.54,17.98 2.463,17.965 2.399,17.921 2.355,17.857 2.34,17.78 2.34,17.78 2.355,17.703 2.399,17.639 2.463,17.595 2.54,17.58 2.54,17.58 2.617,17.595 2.681,17.639 2.725,17.703 2.74,17.78
  Top Layer-L1 keep-out region: 4.01,17.78 3.995,17.857 3.951,17.921 3.887,17.965 3.81,17.98 3.81,17.98 3.733,17.965 3.669,17.921 3.625,17.857 3.61,17.78 3.61,17.78 3.625,17.703 3.669,17.639 3.733,17.595 3.81,17.58 3.81,17.58 3.887,17.595 3.951,17.639 3.995,17.703 4.01,17.78
  Top Layer-L1 keep-out region: 5.28,17.78 5.265,17.857 5.221,17.921 5.157,17.965 5.08,17.98 5.08,17.98 5.003,17.965 4.939,17.921 4.895,17.857 4.88,17.78 4.88,17.78 4.895,17.703 4.939,17.639 5.003,17.595 5.08,17.58 5.08,17.58 5.157,17.595 5.221,17.639 5.265,17.703 5.28,17.78
  Top Layer-L1 keep-out region: 6.55,17.78 6.535,17.857 6.491,17.921 6.427,17.965 6.35,17.98 6.35,17.98 6.273,17.965 6.209,17.921 6.165,17.857 6.15,17.78 6.15,17.78 6.165,17.703 6.209,17.639 6.273,17.595 6.35,17.58 6.35,17.58 6.427,17.595 6.491,17.639 6.535,17.703 6.55,17.78
  Top Layer-L1 keep-out region: 7.82,17.78 7.805,17.857 7.761,17.921 7.697,17.965 7.62,17.98 7.62,17.98 7.543,17.965 7.479,17.921 7.435,17.857 7.42,17.78 7.42,17.78 7.435,17.703 7.479,17.639 7.543,17.595 7.62,17.58 7.62,17.58 7.697,17.595 7.761,17.639 7.805,17.703 7.82,17.78
  Top Layer-L1 keep-out region: 9.09,17.78 9.075,17.857 9.031,17.921 8.967,17.965 8.89,17.98 8.89,17.98 8.813,17.965 8.749,17.921 8.705,17.857 8.69,17.78 8.69,17.78 8.705,17.703 8.749,17.639 8.813,17.595 8.89,17.58 8.89,17.58 8.967,17.595 9.031,17.639 9.075,17.703 9.09,17.78
  Top Layer-L1 keep-out region: 10.36,17.78 10.345,17.857 10.301,17.921 10.237,17.965 10.16,17.98 10.16,17.98 10.083,17.965 10.019,17.921 9.975,17.857 9.96,17.78 9.96,17.78 9.975,17.703 10.019,17.639 10.083,17.595 10.16,17.58 10.16,17.58 10.237,17.595 10.301,17.639 10.345,17.703 10.36,17.78
  Top Layer-L1 keep-out region: 11.63,17.78 11.615,17.857 11.571,17.921 11.507,17.965 11.43,17.98 11.43,17.98 11.353,17.965 11.289,17.921 11.245,17.857 11.23,17.78 11.23,17.78 11.245,17.703 11.289,17.639 11.353,17.595 11.43,17.58 11.43,17.58 11.507,17.595 11.571,17.639 11.615,17.703 11.63,17.78
  Top Layer-L1 keep-out region: 12.9,17.78 12.885,17.857 12.841,17.921 12.777,17.965 12.7,17.98 12.7,17.98 12.623,17.965 12.559,17.921 12.515,17.857 12.5,17.78 12.5,17.78 12.515,17.703 12.559,17.639 12.623,17.595 12.7,17.58 12.7,17.58 12.777,17.595 12.841,17.639 12.885,17.703 12.9,17.78
  Top Layer-L1 keep-out region: 14.17,17.78 14.155,17.857 14.111,17.921 14.047,17.965 13.97,17.98 13.97,17.98 13.893,17.965 13.829,17.921 13.785,17.857 13.77,17.78 13.77,17.78 13.785,17.703 13.829,17.639 13.893,17.595 13.97,17.58 13.97,17.58 14.047,17.595 14.111,17.639 14.155,17.703 14.17,17.78
  Top Layer-L1 keep-out region: 15.44,17.78 15.425,17.857 15.381,17.921 15.317,17.965 15.24,17.98 15.24,17.98 15.163,17.965 15.099,17.921 15.055,17.857 15.04,17.78 15.04,17.78 15.055,17.703 15.099,17.639 15.163,17.595 15.24,17.58 15.24,17.58 15.317,17.595 15.381,17.639 15.425,17.703 15.44,17.78
  Top Layer-L1 keep-out region: 16.71,17.78 16.695,17.857 16.651,17.921 16.587,17.965 16.51,17.98 16.51,17.98 16.433,17.965 16.369,17.921 16.325,17.857 16.31,17.78 16.31,17.78 16.325,17.703 16.369,17.639 16.433,17.595 16.51,17.58 16.51,17.58 16.587,17.595 16.651,17.639 16.695,17.703 16.71,17.78
  Top Layer-L1 keep-out region: -15.04,19.05 -15.055,19.127 -15.099,19.191 -15.163,19.235 -15.24,19.25 -15.24,19.25 -15.317,19.235 -15.381,19.191 -15.425,19.127 -15.44,19.05 -15.44,19.05 -15.425,18.973 -15.381,18.909 -15.317,18.865 -15.24,18.85 -15.24,18.85 -15.163,18.865 -15.099,18.909 -15.055,18.973 -15.04,19.05
  Top Layer-L1 keep-out region: -13.77,19.05 -13.785,19.127 -13.829,19.191 -13.893,19.235 -13.97,19.25 -13.97,19.25 -14.047,19.235 -14.111,19.191 -14.155,19.127 -14.17,19.05 -14.17,19.05 -14.155,18.973 -14.111,18.909 -14.047,18.865 -13.97,18.85 -13.97,18.85 -13.893,18.865 -13.829,18.909 -13.785,18.973 -13.77,19.05
  Top Layer-L1 keep-out region: -12.5,19.05 -12.515,19.127 -12.559,19.191 -12.623,19.235 -12.7,19.25 -12.7,19.25 -12.777,19.235 -12.841,19.191 -12.885,19.127 -12.9,19.05 -12.9,19.05 -12.885,18.973 -12.841,18.909 -12.777,18.865 -12.7,18.85 -12.7,18.85 -12.623,18.865 -12.559,18.909 -12.515,18.973 -12.5,19.05
  Top Layer-L1 keep-out region: -11.23,19.05 -11.245,19.127 -11.289,19.191 -11.353,19.235 -11.43,19.25 -11.43,19.25 -11.507,19.235 -11.571,19.191 -11.615,19.127 -11.63,19.05 -11.63,19.05 -11.615,18.973 -11.571,18.909 -11.507,18.865 -11.43,18.85 -11.43,18.85 -11.353,18.865 -11.289,18.909 -11.245,18.973 -11.23,19.05
  Top Layer-L1 keep-out region: -9.96,19.05 -9.975,19.127 -10.019,19.191 -10.083,19.235 -10.16,19.25 -10.16,19.25 -10.237,19.235 -10.301,19.191 -10.345,19.127 -10.36,19.05 -10.36,19.05 -10.345,18.973 -10.301,18.909 -10.237,18.865 -10.16,18.85 -10.16,18.85 -10.083,18.865 -10.019,18.909 -9.975,18.973 -9.96,19.05
  Top Layer-L1 keep-out region: -8.69,19.05 -8.705,19.127 -8.749,19.191 -8.813,19.235 -8.89,19.25 -8.89,19.25 -8.967,19.235 -9.031,19.191 -9.075,19.127 -9.09,19.05 -9.09,19.05 -9.075,18.973 -9.031,18.909 -8.967,18.865 -8.89,18.85 -8.89,18.85 -8.813,18.865 -8.749,18.909 -8.705,18.973 -8.69,19.05
  Top Layer-L1 keep-out region: -7.42,19.05 -7.435,19.127 -7.479,19.191 -7.543,19.235 -7.62,19.25 -7.62,19.25 -7.697,19.235 -7.761,19.191 -7.805,19.127 -7.82,19.05 -7.82,19.05 -7.805,18.973 -7.761,18.909 -7.697,18.865 -7.62,18.85 -7.62,18.85 -7.543,18.865 -7.479,18.909 -7.435,18.973 -7.42,19.05
  Top Layer-L1 keep-out region: -6.15,19.05 -6.165,19.127 -6.209,19.191 -6.273,19.235 -6.35,19.25 -6.35,19.25 -6.427,19.235 -6.491,19.191 -6.535,19.127 -6.55,19.05 -6.55,19.05 -6.535,18.973 -6.491,18.909 -6.427,18.865 -6.35,18.85 -6.35,18.85 -6.273,18.865 -6.209,18.909 -6.165,18.973 -6.15,19.05
  Top Layer-L1 keep-out region: -4.88,19.05 -4.895,19.127 -4.939,19.191 -5.003,19.235 -5.08,19.25 -5.08,19.25 -5.157,19.235 -5.221,19.191 -5.265,19.127 -5.28,19.05 -5.28,19.05 -5.265,18.973 -5.221,18.909 -5.157,18.865 -5.08,18.85 -5.08,18.85 -5.003,18.865 -4.939,18.909 -4.895,18.973 -4.88,19.05
  Top Layer-L1 keep-out region: -3.61,19.05 -3.625,19.127 -3.669,19.191 -3.733,19.235 -3.81,19.25 -3.81,19.25 -3.887,19.235 -3.951,19.191 -3.995,19.127 -4.01,19.05 -4.01,19.05 -3.995,18.973 -3.951,18.909 -3.887,18.865 -3.81,18.85 -3.81,18.85 -3.733,18.865 -3.669,18.909 -3.625,18.973 -3.61,19.05
  Top Layer-L1 keep-out region: -2.34,19.05 -2.355,19.127 -2.399,19.191 -2.463,19.235 -2.54,19.25 -2.54,19.25 -2.617,19.235 -2.681,19.191 -2.725,19.127 -2.74,19.05 -2.74,19.05 -2.725,18.973 -2.681,18.909 -2.617,18.865 -2.54,18.85 -2.54,18.85 -2.463,18.865 -2.399,18.909 -2.355,18.973 -2.34,19.05
  Top Layer-L1 keep-out region: -1.07,19.05 -1.085,19.127 -1.129,19.191 -1.193,19.235 -1.27,19.25 -1.27,19.25 -1.347,19.235 -1.411,19.191 -1.455,19.127 -1.47,19.05 -1.47,19.05 -1.455,18.973 -1.411,18.909 -1.347,18.865 -1.27,18.85 -1.27,18.85 -1.193,18.865 -1.129,18.909 -1.085,18.973 -1.07,19.05
  Top Layer-L1 keep-out region: 0.2,19.05 0.185,19.127 0.141,19.191 0.077,19.235 0,19.25 0,19.25 -0.077,19.235 -0.141,19.191 -0.185,19.127 -0.2,19.05 -0.2,19.05 -0.185,18.973 -0.141,18.909 -0.077,18.865 0,18.85 0,18.85 0.077,18.865 0.141,18.909 0.185,18.973 0.2,19.05
  Top Layer-L1 keep-out region: 1.47,19.05 1.455,19.127 1.411,19.191 1.347,19.235 1.27,19.25 1.27,19.25 1.193,19.235 1.129,19.191 1.085,19.127 1.07,19.05 1.07,19.05 1.085,18.973 1.129,18.909 1.193,18.865 1.27,18.85 1.27,18.85 1.347,18.865 1.411,18.909 1.455,18.973 1.47,19.05
  Top Layer-L1 keep-out region: 2.74,19.05 2.725,19.127 2.681,19.191 2.617,19.235 2.54,19.25 2.54,19.25 2.463,19.235 2.399,19.191 2.355,19.127 2.34,19.05 2.34,19.05 2.355,18.973 2.399,18.909 2.463,18.865 2.54,18.85 2.54,18.85 2.617,18.865 2.681,18.909 2.725,18.973 2.74,19.05
  Top Layer-L1 keep-out region: 4.01,19.05 3.995,19.127 3.951,19.191 3.887,19.235 3.81,19.25 3.81,19.25 3.733,19.235 3.669,19.191 3.625,19.127 3.61,19.05 3.61,19.05 3.625,18.973 3.669,18.909 3.733,18.865 3.81,18.85 3.81,18.85 3.887,18.865 3.951,18.909 3.995,18.973 4.01,19.05
  Top Layer-L1 keep-out region: 5.28,19.05 5.265,19.127 5.221,19.191 5.157,19.235 5.08,19.25 5.08,19.25 5.003,19.235 4.939,19.191 4.895,19.127 4.88,19.05 4.88,19.05 4.895,18.973 4.939,18.909 5.003,18.865 5.08,18.85 5.08,18.85 5.157,18.865 5.221,18.909 5.265,18.973 5.28,19.05
  Top Layer-L1 keep-out region: 6.55,19.05 6.535,19.127 6.491,19.191 6.427,19.235 6.35,19.25 6.35,19.25 6.273,19.235 6.209,19.191 6.165,19.127 6.15,19.05 6.15,19.05 6.165,18.973 6.209,18.909 6.273,18.865 6.35,18.85 6.35,18.85 6.427,18.865 6.491,18.909 6.535,18.973 6.55,19.05
  Top Layer-L1 keep-out region: 7.82,19.05 7.805,19.127 7.761,19.191 7.697,19.235 7.62,19.25 7.62,19.25 7.543,19.235 7.479,19.191 7.435,19.127 7.42,19.05 7.42,19.05 7.435,18.973 7.479,18.909 7.543,18.865 7.62,18.85 7.62,18.85 7.697,18.865 7.761,18.909 7.805,18.973 7.82,19.05
  Top Layer-L1 keep-out region: 9.09,19.05 9.075,19.127 9.031,19.191 8.967,19.235 8.89,19.25 8.89,19.25 8.813,19.235 8.749,19.191 8.705,19.127 8.69,19.05 8.69,19.05 8.705,18.973 8.749,18.909 8.813,18.865 8.89,18.85 8.89,18.85 8.967,18.865 9.031,18.909 9.075,18.973 9.09,19.05
  Top Layer-L1 keep-out region: 10.36,19.05 10.345,19.127 10.301,19.191 10.237,19.235 10.16,19.25 10.16,19.25 10.083,19.235 10.019,19.191 9.975,19.127 9.96,19.05 9.96,19.05 9.975,18.973 10.019,18.909 10.083,18.865 10.16,18.85 10.16,18.85 10.237,18.865 10.301,18.909 10.345,18.973 10.36,19.05
  Top Layer-L1 keep-out region: 11.63,19.05 11.615,19.127 11.571,19.191 11.507,19.235 11.43,19.25 11.43,19.25 11.353,19.235 11.289,19.191 11.245,19.127 11.23,19.05 11.23,19.05 11.245,18.973 11.289,18.909 11.353,18.865 11.43,18.85 11.43,18.85 11.507,18.865 11.571,18.909 11.615,18.973 11.63,19.05
  Top Layer-L1 keep-out region: 12.9,19.05 12.885,19.127 12.841,19.191 12.777,19.235 12.7,19.25 12.7,19.25 12.623,19.235 12.559,19.191 12.515,19.127 12.5,19.05 12.5,19.05 12.515,18.973 12.559,18.909 12.623,18.865 12.7,18.85 12.7,18.85 12.777,18.865 12.841,18.909 12.885,18.973 12.9,19.05
  Top Layer-L1 keep-out region: 14.17,19.05 14.155,19.127 14.111,19.191 14.047,19.235 13.97,19.25 13.97,19.25 13.893,19.235 13.829,19.191 13.785,19.127 13.77,19.05 13.77,19.05 13.785,18.973 13.829,18.909 13.893,18.865 13.97,18.85 13.97,18.85 14.047,18.865 14.111,18.909 14.155,18.973 14.17,19.05
  Top Layer-L1 keep-out region: 15.44,19.05 15.425,19.127 15.381,19.191 15.317,19.235 15.24,19.25 15.24,19.25 15.163,19.235 15.099,19.191 15.055,19.127 15.04,19.05 15.04,19.05 15.055,18.973 15.099,18.909 15.163,18.865 15.24,18.85 15.24,18.85 15.317,18.865 15.381,18.909 15.425,18.973 15.44,19.05
  Top Layer-L1 keep-out region: -13.77,20.32 -13.785,20.397 -13.829,20.461 -13.893,20.505 -13.97,20.52 -13.97,20.52 -14.047,20.505 -14.111,20.461 -14.155,20.397 -14.17,20.32 -14.17,20.32 -14.155,20.243 -14.111,20.179 -14.047,20.135 -13.97,20.12 -13.97,20.12 -13.893,20.135 -13.829,20.179 -13.785,20.243 -13.77,20.32
  Top Layer-L1 keep-out region: -12.5,20.32 -12.515,20.397 -12.559,20.461 -12.623,20.505 -12.7,20.52 -12.7,20.52 -12.777,20.505 -12.841,20.461 -12.885,20.397 -12.9,20.32 -12.9,20.32 -12.885,20.243 -12.841,20.179 -12.777,20.135 -12.7,20.12 -12.7,20.12 -12.623,20.135 -12.559,20.179 -12.515,20.243 -12.5,20.32
  Top Layer-L1 keep-out region: -11.23,20.32 -11.245,20.397 -11.289,20.461 -11.353,20.505 -11.43,20.52 -11.43,20.52 -11.507,20.505 -11.571,20.461 -11.615,20.397 -11.63,20.32 -11.63,20.32 -11.615,20.243 -11.571,20.179 -11.507,20.135 -11.43,20.12 -11.43,20.12 -11.353,20.135 -11.289,20.179 -11.245,20.243 -11.23,20.32
  Top Layer-L1 keep-out region: -9.96,20.32 -9.975,20.397 -10.019,20.461 -10.083,20.505 -10.16,20.52 -10.16,20.52 -10.237,20.505 -10.301,20.461 -10.345,20.397 -10.36,20.32 -10.36,20.32 -10.345,20.243 -10.301,20.179 -10.237,20.135 -10.16,20.12 -10.16,20.12 -10.083,20.135 -10.019,20.179 -9.975,20.243 -9.96,20.32
  Top Layer-L1 keep-out region: -8.69,20.32 -8.705,20.397 -8.749,20.461 -8.813,20.505 -8.89,20.52 -8.89,20.52 -8.967,20.505 -9.031,20.461 -9.075,20.397 -9.09,20.32 -9.09,20.32 -9.075,20.243 -9.031,20.179 -8.967,20.135 -8.89,20.12 -8.89,20.12 -8.813,20.135 -8.749,20.179 -8.705,20.243 -8.69,20.32
  Top Layer-L1 keep-out region: -7.42,20.32 -7.435,20.397 -7.479,20.461 -7.543,20.505 -7.62,20.52 -7.62,20.52 -7.697,20.505 -7.761,20.461 -7.805,20.397 -7.82,20.32 -7.82,20.32 -7.805,20.243 -7.761,20.179 -7.697,20.135 -7.62,20.12 -7.62,20.12 -7.543,20.135 -7.479,20.179 -7.435,20.243 -7.42,20.32
  Top Layer-L1 keep-out region: -6.15,20.32 -6.165,20.397 -6.209,20.461 -6.273,20.505 -6.35,20.52 -6.35,20.52 -6.427,20.505 -6.491,20.461 -6.535,20.397 -6.55,20.32 -6.55,20.32 -6.535,20.243 -6.491,20.179 -6.427,20.135 -6.35,20.12 -6.35,20.12 -6.273,20.135 -6.209,20.179 -6.165,20.243 -6.15,20.32
  Top Layer-L1 keep-out region: -4.88,20.32 -4.895,20.397 -4.939,20.461 -5.003,20.505 -5.08,20.52 -5.08,20.52 -5.157,20.505 -5.221,20.461 -5.265,20.397 -5.28,20.32 -5.28,20.32 -5.265,20.243 -5.221,20.179 -5.157,20.135 -5.08,20.12 -5.08,20.12 -5.003,20.135 -4.939,20.179 -4.895,20.243 -4.88,20.32
  Top Layer-L1 keep-out region: -3.61,20.32 -3.625,20.397 -3.669,20.461 -3.733,20.505 -3.81,20.52 -3.81,20.52 -3.887,20.505 -3.951,20.461 -3.995,20.397 -4.01,20.32 -4.01,20.32 -3.995,20.243 -3.951,20.179 -3.887,20.135 -3.81,20.12 -3.81,20.12 -3.733,20.135 -3.669,20.179 -3.625,20.243 -3.61,20.32
  Top Layer-L1 keep-out region: -2.34,20.32 -2.355,20.397 -2.399,20.461 -2.463,20.505 -2.54,20.52 -2.54,20.52 -2.617,20.505 -2.681,20.461 -2.725,20.397 -2.74,20.32 -2.74,20.32 -2.725,20.243 -2.681,20.179 -2.617,20.135 -2.54,20.12 -2.54,20.12 -2.463,20.135 -2.399,20.179 -2.355,20.243 -2.34,20.32
  Top Layer-L1 keep-out region: -1.07,20.32 -1.085,20.397 -1.129,20.461 -1.193,20.505 -1.27,20.52 -1.27,20.52 -1.347,20.505 -1.411,20.461 -1.455,20.397 -1.47,20.32 -1.47,20.32 -1.455,20.243 -1.411,20.179 -1.347,20.135 -1.27,20.12 -1.27,20.12 -1.193,20.135 -1.129,20.179 -1.085,20.243 -1.07,20.32
  Top Layer-L1 keep-out region: 0.2,20.32 0.185,20.397 0.141,20.461 0.077,20.505 0,20.52 0,20.52 -0.077,20.505 -0.141,20.461 -0.185,20.397 -0.2,20.32 -0.2,20.32 -0.185,20.243 -0.141,20.179 -0.077,20.135 0,20.12 0,20.12 0.077,20.135 0.141,20.179 0.185,20.243 0.2,20.32
  Top Layer-L1 keep-out region: 1.47,20.32 1.455,20.397 1.411,20.461 1.347,20.505 1.27,20.52 1.27,20.52 1.193,20.505 1.129,20.461 1.085,20.397 1.07,20.32 1.07,20.32 1.085,20.243 1.129,20.179 1.193,20.135 1.27,20.12 1.27,20.12 1.347,20.135 1.411,20.179 1.455,20.243 1.47,20.32
  Top Layer-L1 keep-out region: 2.74,20.32 2.725,20.397 2.681,20.461 2.617,20.505 2.54,20.52 2.54,20.52 2.463,20.505 2.399,20.461 2.355,20.397 2.34,20.32 2.34,20.32 2.355,20.243 2.399,20.179 2.463,20.135 2.54,20.12 2.54,20.12 2.617,20.135 2.681,20.179 2.725,20.243 2.74,20.32
  Top Layer-L1 keep-out region: 4.01,20.32 3.995,20.397 3.951,20.461 3.887,20.505 3.81,20.52 3.81,20.52 3.733,20.505 3.669,20.461 3.625,20.397 3.61,20.32 3.61,20.32 3.625,20.243 3.669,20.179 3.733,20.135 3.81,20.12 3.81,20.12 3.887,20.135 3.951,20.179 3.995,20.243 4.01,20.32
  Top Layer-L1 keep-out region: 5.28,20.32 5.265,20.397 5.221,20.461 5.157,20.505 5.08,20.52 5.08,20.52 5.003,20.505 4.939,20.461 4.895,20.397 4.88,20.32 4.88,20.32 4.895,20.243 4.939,20.179 5.003,20.135 5.08,20.12 5.08,20.12 5.157,20.135 5.221,20.179 5.265,20.243 5.28,20.32
  Top Layer-L1 keep-out region: 6.55,20.32 6.535,20.397 6.491,20.461 6.427,20.505 6.35,20.52 6.35,20.52 6.273,20.505 6.209,20.461 6.165,20.397 6.15,20.32 6.15,20.32 6.165,20.243 6.209,20.179 6.273,20.135 6.35,20.12 6.35,20.12 6.427,20.135 6.491,20.179 6.535,20.243 6.55,20.32
  Top Layer-L1 keep-out region: 7.82,20.32 7.805,20.397 7.761,20.461 7.697,20.505 7.62,20.52 7.62,20.52 7.543,20.505 7.479,20.461 7.435,20.397 7.42,20.32 7.42,20.32 7.435,20.243 7.479,20.179 7.543,20.135 7.62,20.12 7.62,20.12 7.697,20.135 7.761,20.179 7.805,20.243 7.82,20.32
